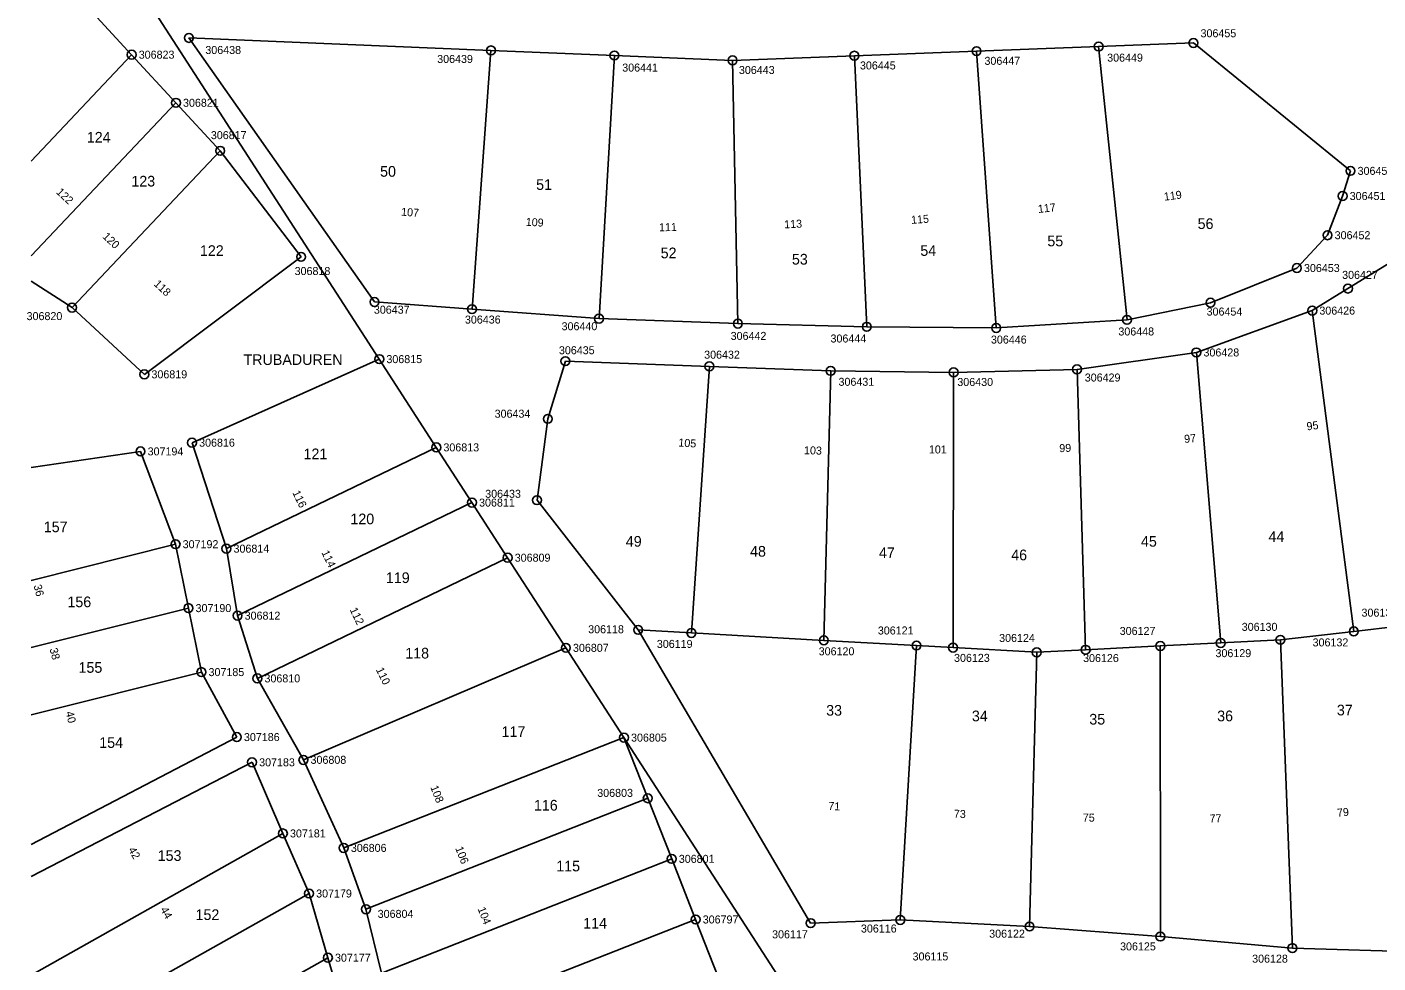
# Model space of a CAD drawing. Extents: x 141995 to 152570, y 6580184 to 6586000.
# Drawn here: x 141999.5 to 142151.4, y 6585489.6 to 6585594.9 of the extents above; entities that cross this region are included whole.
import ezdxf

# ---------------------------------------------------------------- set-up
doc = ezdxf.new("R2010")
doc.units = 0
for name, color, linetype in [('Level 10', 7, 'Continuous'), ('Level 50', 7, 'Continuous'), ('Level 51', 7, 'Continuous'), ('Level 53', 7, 'Continuous'), ('Level 54', 7, 'Continuous'), ('Level 7', 7, 'Continuous')]:
    doc.layers.add(name, color=color, linetype=linetype)

msp = doc.modelspace()

# ---------------------------------------------------------------- linework, layer by layer
at = {"layer": 'Level 10'}
for centre in [(142017.73, 6585593.7), (142120.03, 6585592.73), (142130.69, 6585593.13), (142011.29, 6585591.81), (142051.7, 6585592.29), (142065.58, 6585591.72), (142092.56, 6585591.69), (142106.3, 6585592.21), (142078.86, 6585591.17), (142016.27, 6585586.4), (142021.25, 6585581), (142148.35, 6585578.74), (142147.46, 6585575.91), (142145.77, 6585571.5), (142030.35, 6585569.07), (142142.32, 6585567.81), (142148.06, 6585565.5), (142038.6, 6585563.99), (142132.61, 6585563.91), (142004.59, 6585563.36), (142049.57, 6585563.18), (142144.05, 6585563.02), (142063.85, 6585562.12), (142079.46, 6585561.56), (142093.96, 6585561.2), (142108.51, 6585561.07), (142123.22, 6585561.98), (142131.02, 6585558.31), (142039.14, 6585557.56), (142060.07, 6585557.33), (142076.26, 6585556.75), (142117.6, 6585556.41), (142012.72, 6585555.85), (142089.9, 6585556.24), (142103.72, 6585556.07), (142058.09, 6585550.84), (142012.29, 6585547.18), (142018.08, 6585548.16), (142045.55, 6585547.63), (142049.56, 6585541.42), (142056.88, 6585541.69), (142016.23, 6585536.74), (142021.95, 6585536.24), (142053.57, 6585535.22), (142017.68, 6585529.55), (142023.2, 6585528.7), (142068.25, 6585527.1), (142074.24, 6585526.76), (142089.13, 6585525.92), (142140.47, 6585525.98), (142148.72, 6585526.93), (142060.12, 6585525.08), (142099.55, 6585525.34), (142103.66, 6585525.11), (142113.07, 6585524.58), (142118.56, 6585524.86), (142126.96, 6585525.29), (142133.76, 6585525.63), (142019.14, 6585522.35), (142025.43, 6585521.64), (142023.12, 6585515.04), (142066.65, 6585514.98), (142030.61, 6585512.47), (142024.83, 6585512.2), (142069.33, 6585508.16), (142028.3, 6585504.2), (142035.14, 6585502.57), (142072.02, 6585501.34), (142031.24, 6585497.44), (142037.64, 6585495.67), (142074.71, 6585494.52), (142087.64, 6585494.11), (142097.72, 6585494.47), (142112.26, 6585493.73), (142126.97, 6585492.6), (142141.82, 6585491.3), (142033.36, 6585490.22)]:
    msp.add_circle(centre, 0.5, dxfattribs=at)
at = {"layer": 'Level 7'}
for points in [[(142000, 6585618.14), (142039.14, 6585557.56)], [(142002.2, 6585601.69), (142011.29, 6585591.81)], [(142038.6, 6585563.99), (142017.73, 6585593.7)], [(142017.73, 6585593.7), (142051.7, 6585592.29)], [(142000, 6585579.85), (142011.29, 6585591.81)], [(142011.29, 6585591.81), (142016.27, 6585586.4)], [(142051.7, 6585592.29), (142049.57, 6585563.18)], [(142051.7, 6585592.29), (142065.58, 6585591.72)], [(142065.58, 6585591.72), (142063.85, 6585562.12)], [(142065.58, 6585591.72), (142078.86, 6585591.17)], [(142092.56, 6585591.69), (142106.3, 6585592.21)], [(142106.3, 6585592.21), (142120.03, 6585592.73)], [(142106.3, 6585592.21), (142108.51, 6585561.07)], [(142120.03, 6585592.73), (142130.69, 6585593.13)], [(142120.03, 6585592.73), (142123.22, 6585561.98)], [(142130.69, 6585593.13), (142148.35, 6585578.74)], [(142078.86, 6585591.17), (142092.56, 6585591.69)], [(142078.86, 6585591.17), (142079.46, 6585561.56)], [(142092.56, 6585591.69), (142093.96, 6585561.2)], [(142000, 6585569.17), (142016.27, 6585586.4)], [(142016.27, 6585586.4), (142021.25, 6585581)], [(142004.59, 6585563.36), (142021.25, 6585581)], [(142021.25, 6585581), (142030.35, 6585569.07)], [(142148.35, 6585578.74), (142147.46, 6585575.91)], [(142147.46, 6585575.91), (142145.77, 6585571.5)], [(142145.77, 6585571.5), (142142.32, 6585567.81)], [(142148.06, 6585565.5), (142156.73, 6585570.85)], [(142030.35, 6585569.07), (142012.72, 6585555.85)], [(142142.32, 6585567.81), (142132.61, 6585563.91)], [(142004.59, 6585563.36), (142000, 6585566.32)], [(142144.05, 6585563.02), (142148.06, 6585565.5)], [(142012.72, 6585555.85), (142004.59, 6585563.36)], [(142049.57, 6585563.18), (142038.6, 6585563.99)], [(142063.85, 6585562.12), (142049.57, 6585563.18)], [(142132.61, 6585563.91), (142123.22, 6585561.98)], [(142131.02, 6585558.31), (142144.05, 6585563.02)], [(142148.72, 6585526.93), (142144.05, 6585563.02)], [(142079.46, 6585561.56), (142063.85, 6585562.12)], [(142093.96, 6585561.2), (142079.46, 6585561.56)], [(142123.22, 6585561.98), (142108.51, 6585561.07)], [(142108.51, 6585561.07), (142093.96, 6585561.2)], [(142117.6, 6585556.41), (142131.02, 6585558.31)], [(142133.76, 6585525.63), (142131.02, 6585558.31)], [(142039.14, 6585557.56), (142018.08, 6585548.16)], [(142039.14, 6585557.56), (142045.55, 6585547.63)], [(142058.09, 6585550.84), (142060.07, 6585557.33)], [(142060.07, 6585557.33), (142076.26, 6585556.75)], [(142074.24, 6585526.76), (142076.26, 6585556.75)], [(142076.26, 6585556.75), (142089.9, 6585556.24)], [(142089.13, 6585525.92), (142089.9, 6585556.24)], [(142089.9, 6585556.24), (142103.72, 6585556.07)], [(142103.66, 6585525.11), (142103.72, 6585556.07)], [(142103.72, 6585556.07), (142117.6, 6585556.41)], [(142118.56, 6585524.86), (142117.6, 6585556.41)], [(142056.88, 6585541.69), (142058.09, 6585550.84)], [(142018.08, 6585548.16), (142021.95, 6585536.24)], [(142000, 6585545.36), (142012.29, 6585547.18)], [(142012.29, 6585547.18), (142016.23, 6585536.74)], [(142021.95, 6585536.24), (142045.55, 6585547.63)], [(142045.55, 6585547.63), (142049.56, 6585541.42)], [(142068.25, 6585527.1), (142056.88, 6585541.69)], [(142023.2, 6585528.7), (142049.56, 6585541.42)], [(142049.56, 6585541.42), (142053.57, 6585535.22)], [(142000, 6585532.66), (142016.23, 6585536.74)], [(142016.23, 6585536.74), (142017.68, 6585529.55)], [(142021.95, 6585536.24), (142023.2, 6585528.7)], [(142025.43, 6585521.64), (142053.57, 6585535.22)], [(142053.57, 6585535.22), (142060.12, 6585525.08)], [(142000, 6585525.1), (142017.68, 6585529.55)], [(142017.68, 6585529.55), (142019.14, 6585522.35)], [(142023.2, 6585528.7), (142025.43, 6585521.64)], [(142068.25, 6585527.1), (142074.24, 6585526.76)], [(142087.64, 6585494.11), (142068.25, 6585527.1)], [(142074.24, 6585526.76), (142089.13, 6585525.92)], [(142140.47, 6585525.98), (142148.72, 6585526.93)], [(142148.72, 6585526.93), (142153.77, 6585527.51)], [(142030.61, 6585512.47), (142060.12, 6585525.08)], [(142060.12, 6585525.08), (142066.65, 6585514.98)], [(142089.13, 6585525.92), (142099.55, 6585525.34)], [(142099.55, 6585525.34), (142097.72, 6585494.47)], [(142099.55, 6585525.34), (142103.66, 6585525.11)], [(142103.66, 6585525.11), (142113.07, 6585524.58)], [(142118.56, 6585524.86), (142126.96, 6585525.29)], [(142126.96, 6585525.29), (142133.76, 6585525.63)], [(142126.96, 6585525.29), (142126.97, 6585492.6)], [(142133.76, 6585525.63), (142140.47, 6585525.98)], [(142140.47, 6585525.98), (142141.82, 6585491.3)], [(142113.07, 6585524.58), (142112.26, 6585493.73)], [(142113.07, 6585524.58), (142118.56, 6585524.86)], [(142000, 6585517.54), (142019.14, 6585522.35)], [(142019.14, 6585522.35), (142023.12, 6585515.04)], [(142025.43, 6585521.64), (142030.61, 6585512.47)], [(142023.12, 6585515.04), (142000, 6585502.95)], [(142035.14, 6585502.57), (142066.65, 6585514.98)], [(142069.33, 6585508.16), (142066.65, 6585514.98)], [(142066.65, 6585514.98), (142120.37, 6585431.82)], [(142000, 6585499.34), (142024.83, 6585512.2)], [(142024.83, 6585512.2), (142028.3, 6585504.2)], [(142030.61, 6585512.47), (142035.14, 6585502.57)], [(142037.64, 6585495.67), (142069.33, 6585508.16)], [(142072.02, 6585501.34), (142069.33, 6585508.16)], [(142000, 6585488.26), (142028.3, 6585504.2)], [(142028.3, 6585504.2), (142031.24, 6585497.44)], [(142035.14, 6585502.57), (142037.64, 6585495.67)], [(142039.39, 6585488.48), (142072.02, 6585501.34)], [(142074.71, 6585494.52), (142072.02, 6585501.34)], [(142000.06, 6585479.88), (142031.24, 6585497.44)], [(142031.24, 6585497.44), (142033.36, 6585490.22)], [(142037.64, 6585495.67), (142039.39, 6585488.48)], [(142042.4, 6585481.79), (142074.71, 6585494.52)], [(142077.29, 6585487.95), (142074.71, 6585494.52)], [(142097.72, 6585494.47), (142087.64, 6585494.11)], [(142112.26, 6585493.73), (142097.72, 6585494.47)], [(142126.97, 6585492.6), (142112.26, 6585493.73)], [(142141.82, 6585491.3), (142126.97, 6585492.6)], [(142003.81, 6585473.58), (142033.36, 6585490.22)], [(142033.36, 6585490.22), (142035.48, 6585483)], [(142156.93, 6585490.84), (142141.82, 6585491.3)]]:
    msp.add_lwpolyline(points, dxfattribs=at)

# ---------------------------------------------------------------- texts
at = {"layer": 'Level 50'}
msp.add_text('TRUBADUREN', height=1.2, rotation=0.0527, dxfattribs=at).set_placement((142023.87, 6585556.9))
at = {"layer": 'Level 51'}
for s, p in [('124', (142006.25, 6585581.92)), ('123', (142011.26, 6585576.98)), ('50', (142039.23, 6585578.08)), ('51', (142056.78, 6585576.6)), ('56', (142131.16, 6585572.2)), ('55', (142114.26, 6585570.25)), ('122', (142018.97, 6585569.17)), ('52', (142070.78, 6585568.91)), ('53', (142085.54, 6585568.2)), ('54', (142099.98, 6585569.18)), ('121', (142030.62, 6585546.3)), ('120', (142035.89, 6585538.98)), ('157', (142001.41, 6585538.09)), ('49', (142066.86, 6585536.46)), ('45', (142124.79, 6585536.46)), ('44', (142139.13, 6585537)), ('48', (142080.83, 6585535.34)), ('47', (142095.33, 6585535.18)), ('46', (142110.2, 6585534.93)), ('119', (142039.88, 6585532.37)), ('156', (142004.07, 6585529.65)), ('118', (142042.06, 6585523.88)), ('155', (142005.32, 6585522.27)), ('33', (142089.39, 6585517.45)), ('34', (142105.78, 6585516.82)), ('35', (142118.98, 6585516.45)), ('36', (142133.36, 6585516.82)), ('37', (142146.82, 6585517.48)), ('117', (142052.89, 6585515.05)), ('154', (142007.65, 6585513.82)), ('116', (142056.53, 6585506.77)), ('153', (142014.22, 6585501.11)), ('115', (142059.04, 6585499.93)), ('152', (142018.48, 6585494.46)), ('114', (142062.07, 6585493.5))]:
    msp.add_text(s, height=1.2, rotation=0.0527, dxfattribs=at).set_placement(p)
at = {"layer": 'Level 53'}
for s, p in [('306455', (142131.49, 6585593.77)), ('306823', (142012.09, 6585591.36)), ('306438', (142019.58, 6585591.89)), ('306439', (142045.65, 6585590.88)), ('306449', (142120.99, 6585591.03)), ('306441', (142066.46, 6585589.91)), ('306443', (142079.58, 6585589.64)), ('306445', (142093.19, 6585590.15)), ('306447', (142107.19, 6585590.67)), ('306821', (142017.07, 6585585.95)), ('306817', (142020.2, 6585582.31)), ('306450', (142149.15, 6585578.29)), ('306451', (142148.26, 6585575.46)), ('306452', (142146.57, 6585571.05)), ('306818', (142029.62, 6585567.02)), ('306453', (142143.12, 6585567.36)), ('306427', (142147.41, 6585566.59)), ('306820', (141999.48, 6585561.95)), ('306437', (142038.53, 6585562.67)), ('306454', (142132.17, 6585562.46)), ('306426', (142144.85, 6585562.57)), ('306436', (142048.77, 6585561.56)), ('306440', (142059.64, 6585560.81)), ('306442', (142078.65, 6585559.72)), ('306444', (142089.88, 6585559.43)), ('306446', (142107.92, 6585559.31)), ('306448', (142122.25, 6585560.22)), ('306435', (142059.34, 6585558.11)), ('306432', (142075.67, 6585557.61)), ('306428', (142131.82, 6585557.86)), ('306815', (142039.94, 6585557.11)), ('306819', (142013.52, 6585555.4)), ('306431', (142090.78, 6585554.56)), ('306430', (142104.14, 6585554.54)), ('306429', (142118.47, 6585555.04)), ('306434', (142052.11, 6585550.97)), ('306816', (142018.88, 6585547.71)), ('306813', (142046.35, 6585547.18)), ('307194', (142013.09, 6585546.73)), ('306811', (142050.36, 6585540.97)), ('306433', (142051.05, 6585541.96)), ('307192', (142017.03, 6585536.29)), ('306814', (142022.75, 6585535.79)), ('306809', (142054.37, 6585534.77)), ('307190', (142018.48, 6585529.1)), ('306133', (142149.59, 6585528.59)), ('306812', (142024, 6585528.25)), ('306130', (142136.12, 6585526.99)), ('306118', (142062.63, 6585526.72)), ('306121', (142095.2, 6585526.58)), ('306124', (142108.84, 6585525.74)), ('306127', (142122.4, 6585526.53)), ('306807', (142060.92, 6585524.63)), ('306119', (142070.35, 6585525.07)), ('306120', (142088.55, 6585524.24)), ('306129', (142133.17, 6585524.03)), ('306132', (142144.09, 6585525.24)), ('306123', (142103.77, 6585523.5)), ('306126', (142118.28, 6585523.48)), ('307185', (142019.94, 6585521.9)), ('306810', (142026.23, 6585521.19)), ('307186', (142023.92, 6585514.59)), ('306805', (142067.45, 6585514.53)), ('306808', (142031.41, 6585512.03)), ('307183', (142025.63, 6585511.75)), ('306803', (142063.65, 6585508.31)), ('307181', (142029.1, 6585503.75)), ('306806', (142035.94, 6585502.12)), ('306801', (142072.82, 6585500.89)), ('307179', (142032.04, 6585496.99)), ('306804', (142038.96, 6585494.7)), ('306797', (142075.51, 6585494.07)), ('306117', (142083.31, 6585492.4)), ('306116', (142093.3, 6585493.05)), ('306122', (142107.72, 6585492.47)), ('306125', (142122.44, 6585491.04)), ('307177', (142034.16, 6585489.77)), ('306115', (142099.11, 6585489.91)), ('306128', (142137.29, 6585489.66))]:
    msp.add_text(s, height=0.9, rotation=0.0527, dxfattribs=at).set_placement(p)
at = {"layer": 'Level 54'}
for s, rotation, p in [('122', 316.7265, (142002.75, 6585576.27)), ('119', 7.4717, (142127.43, 6585575.38)), ('117', 6.0887, (142113.25, 6585574)), ('107', 355.7327, (142041.57, 6585573.71)), ('115', 4.1707, (142098.97, 6585572.77)), ('109', 356.7367, (142055.59, 6585572.57)), ('111', 1.1427, (142070.6, 6585571.94)), ('113', 2.6097, (142084.69, 6585572.27)), ('120', 316.7265, (142007.95, 6585571.27)), ('118', 316.7265, (142013.72, 6585565.93)), ('95', 7.3937, (142143.47, 6585549.54)), ('105', 356.2027, (142072.75, 6585547.74)), ('103', 358.4087, (142086.89, 6585546.87)), ('101', 359.9047, (142100.94, 6585546.95)), ('99', 1.8787, (142115.62, 6585547.09)), ('97', 4.8477, (142129.68, 6585548.13)), ('116', 295.6947, (142029.34, 6585542.54)), ('114', 295.6947, (142032.61, 6585535.81)), ('36', 284.1554, (142000.26, 6585532.09)), ('112', 295.6947, (142035.79, 6585529.37)), ('38', 284.1554, (142002.06, 6585524.96)), ('110', 295.6947, (142038.74, 6585522.63)), ('40', 284.1554, (142003.86, 6585517.83)), ('108', 291.4636, (142044.86, 6585509.41)), ('71', 356.5417, (142089.61, 6585506.86)), ('73', 358.1537, (142103.74, 6585505.97)), ('79', 5.0827, (142146.87, 6585506.07)), ('75', 359.8987, (142118.25, 6585505.53)), ('77', 2.1887, (142132.52, 6585505.42)), ('42', 299.4248, (142010.88, 6585502.37)), ('106', 291.4636, (142047.66, 6585502.54)), ('44', 299.4248, (142014.49, 6585495.64)), ('104', 291.4636, (142050.18, 6585495.73))]:
    msp.add_text(s, height=0.9, rotation=rotation, dxfattribs=at).set_placement(p)

doc.saveas('drawing.dxf')
